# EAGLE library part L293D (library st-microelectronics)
PUSH-PULL 4 CHANNEL DRIVER
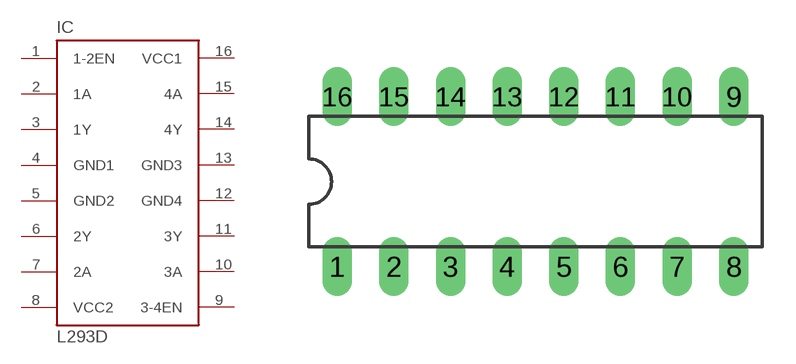
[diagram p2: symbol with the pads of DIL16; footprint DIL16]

Designator prefix IC

## L293D (MPN: L293D; OC_FARNELL: 9589619; OC_NEWARK: 56P8249)  [DIL16]
1  1-2EN  in
2  1A  in
3  1Y  out
4  GND1  pwr
5  GND2  pwr
6  2Y  out
7  2A  in
8  VCC2  pwr
9  3-4EN  in
10  3A  in
11  3Y  out
12  GND4  pwr
13  GND3  pwr
14  4Y  out
15  4A  in
16  VCC1  pwr

## Footprint DIL16 (pad centres in mm)
Dual In Line Package
drill 0.813 long: 1 -8.89,-3.81; 2 -6.35,-3.81; 3 -3.81,-3.81; 4 -1.27,-3.81; 5 1.27,-3.81; 6 3.81,-3.81; 7 6.35,-3.81; 8 8.89,-3.81; 9 8.89,3.81; 10 6.35,3.81; 11 3.81,3.81; 12 1.27,3.81; 13 -1.27,3.81; 14 -3.81,3.81; 15 -6.35,3.81; 16 -8.89,3.81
